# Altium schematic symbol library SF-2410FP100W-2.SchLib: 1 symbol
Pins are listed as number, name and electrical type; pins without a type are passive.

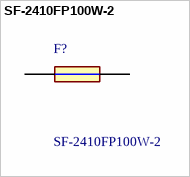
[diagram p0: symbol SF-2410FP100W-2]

## SF-2410FP100W-2
designator F?
Surface Mount Fuses 1.0A Fast Acting 2410 SinglFuse; Manufacturer_Name: Bourns; Geometry.Height: 2.36mm
footprint SF2410FP100W2
pins: 1, 2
